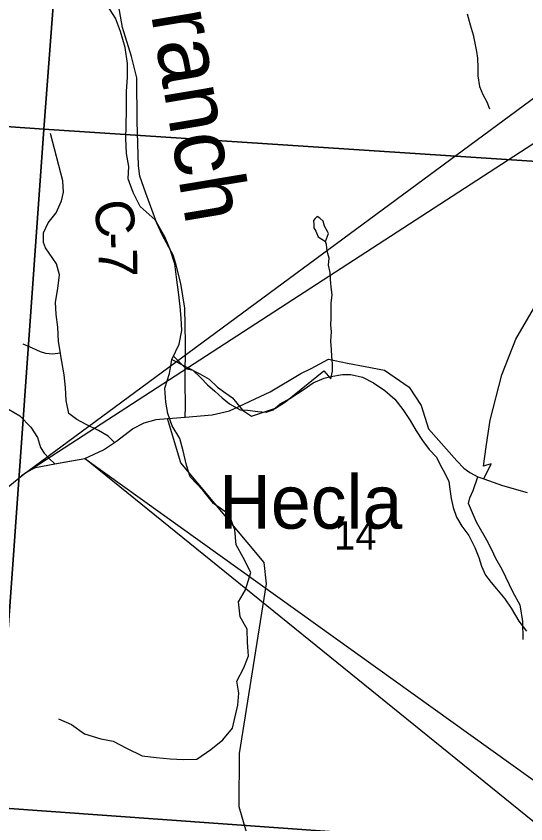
# Model space of a CAD drawing. Extents: x 0 to 34, y 0 to 22.
# Drawn here: x 4.64 to 5.391, y 16.363 to 17.554 of the extents above; entities that cross this region are included whole.
import ezdxf

# ---------------------------------------------------------------- set-up
doc = ezdxf.new("R2010")
doc.units = 0
for name, color, linetype in [('GM_X_Corporation', 7, 'Continuous'), ('GM_X_County_Road', 7, 'Continuous'), ('GM_X_County_Road_Text', 7, 'Continuous'), ('GM_X_Minor_Lake', 7, 'Continuous'), ('GM_X_Minor_River', 7, 'Continuous'), ('GM_X_Minor_River_Text', 7, 'Continuous'), ('GM_X_Section_Text', 7, 'Continuous'), ('GM_X_State_Route', 7, 'Continuous'), ('GM_X_Township_Road', 7, 'Continuous'), ('GM_X_Unincorporated_Location', 7, 'Continuous'), ('GM_X_Unincorporated_Text', 7, 'Continuous'), ('SH_Text', 7, 'Continuous')]:
    doc.layers.add(name, color=color, linetype=linetype)

msp = doc.modelspace()

# ---------------------------------------------------------------- linework, layer by layer
at = {"layer": 'GM_X_Corporation'}
for points in [[(4.7598, 18.4308), (4.6804, 17.3872), (3.6641, 17.4586), (3.742, 18.4953)], [(4.7598, 18.4308), (5.775, 18.3681), (5.6845, 17.321), (4.6804, 17.3872)], [(3.6641, 17.4586), (4.6804, 17.3872), (4.6087, 16.3871), (3.6056, 16.4577)], [(4.6804, 17.3872), (5.6845, 17.321), (5.612, 16.3148), (5.6072, 16.3154), (4.6087, 16.3871)], [(4.6087, 16.3871), (5.6072, 16.3154), (5.5415, 15.2956), (4.5353, 15.3628)]]:
    msp.add_lwpolyline(points, close=True, dxfattribs=at)
at = {"layer": 'GM_X_County_Road'}
for points in [[(4.8886, 16.9624), (4.8894, 16.9787), (4.8887, 17.0141), (4.8892, 17.0726), (4.8884, 17.1231), (4.8823, 17.1597), (4.875, 17.1887), (4.8711, 17.2013), (4.8646, 17.2132), (4.8547, 17.2313), (4.8468, 17.2482), (4.831, 17.2926), (4.8221, 17.3179), (4.8198, 17.3327), (4.8178, 17.3985), (4.8173, 17.4627), (4.8096, 17.494), (4.7965, 17.5369), (4.7918, 17.5617), (4.7849, 17.5918), (4.7834, 17.6281)], [(4.3389, 17.135), (4.339, 17.1096), (4.352, 17.0964), (4.3677, 17.087), (4.388, 17.0816), (4.4115, 17.0785), (4.4326, 17.0754), (4.4522, 17.0712), (4.4713, 17.062), (4.4975, 17.0467), (4.5233, 17.0271), (4.5427, 17.0142), (4.5599, 17.0055), (4.599, 16.9891), (4.62, 16.9791), (4.6451, 16.9642), (4.6614, 16.9475), (4.6713, 16.9325), (4.6755, 16.9179), (4.681, 16.9095), (4.6884, 16.9017), (4.6965, 16.8937)], [(4.7848, 16.9253), (4.7877, 16.9272), (4.8111, 16.9451), (4.8283, 16.9539), (4.8458, 16.9589), (4.8625, 16.9605)], [(4.8625, 16.9605), (4.87, 16.9612), (4.8886, 16.9624)], [(4.9838, 16.3357), (4.9681, 16.3879), (4.9688, 16.4668), (5.0088, 16.717), (5.0052, 16.7481), (4.8823, 16.8951), (4.8625, 16.9605)], [(4.6965, 16.8937), (4.7043, 16.8952), (4.7411, 16.9014), (4.7682, 16.9143), (4.7848, 16.9253)]]:
    msp.add_lwpolyline(points, dxfattribs=at)
at = {"layer": 'GM_X_Minor_Lake'}
for points in [[(5.0832, 17.2583), (5.0802, 17.2553), (5.0779, 17.2522), (5.0782, 17.2462), (5.0782, 17.2416), (5.0812, 17.2367), (5.0846, 17.2283), (5.0956, 17.2214)], [(5.0956, 17.2214), (5.0998, 17.2332), (5.0986, 17.2362), (5.0941, 17.2438), (5.0923, 17.2514), (5.0873, 17.256), (5.0832, 17.2583)]]:
    msp.add_lwpolyline(points, dxfattribs=at)
at = {"layer": 'GM_X_Minor_River'}
for points in [[(4.7023, 16.5179), (4.7212, 16.5095), (4.7405, 16.4958), (4.7643, 16.4885), (4.7825, 16.4851), (4.8025, 16.4748), (4.8252, 16.4634), (4.846, 16.4607), (4.8668, 16.4591), (4.8865, 16.458), (4.9058, 16.4583), (4.9267, 16.4728), (4.9445, 16.4868), (4.9585, 16.5039), (4.9662, 16.5381), (4.9677, 16.5556), (4.9647, 16.5731), (4.975, 16.5929), (4.9822, 16.6108), (4.9804, 16.6302), (4.9801, 16.6499), (4.9699, 16.6682), (4.9673, 16.6903), (4.9779, 16.7078), (4.9856, 16.7336), (4.9743, 16.7557), (4.9637, 16.7743), (4.9619, 16.7964), (4.9536, 16.8188), (4.9305, 16.8352), (4.915, 16.855), (4.8962, 16.8744), (4.8909, 16.8919), (4.886, 16.9129), (4.8808, 16.9311), (4.8695, 16.9498), (4.8631, 16.9677), (4.8605, 16.9848), (4.8586, 17.0053), (4.8655, 17.0266), (4.8693, 17.0476), (4.88, 17.07), (4.8838, 17.0902), (4.8827, 17.1084), (4.8816, 17.1255), (4.879, 17.1469), (4.8764, 17.1651), (4.8734, 17.1887), (4.8666, 17.2097), (4.8587, 17.2283), (4.8444, 17.2531), (4.8225, 17.2732), (4.8119, 17.2934), (4.8048, 17.314), (4.8056, 17.3319), (4.8022, 17.3513), (4.8011, 17.3737), (4.8016, 17.3909), (4.8024, 17.4167), (4.8021, 17.4426), (4.8036, 17.4636), (4.804, 17.4837), (4.8003, 17.5073), (4.7936, 17.5309), (4.786, 17.5504), (4.774, 17.5698)], [(5.3043, 17.5571), (5.3089, 17.5407), (5.313, 17.5259), (5.3161, 17.5111), (5.3183, 17.5013), (5.3195, 17.4914), (5.3202, 17.4774), (5.3202, 17.4656), (5.3225, 17.45), (5.3274, 17.4383), (5.3331, 17.4272), (5.3372, 17.417)], [(5.093, 17.0309), (5.1034, 17.0191), (5.1057, 17.0301), (5.1061, 17.0411), (5.105, 17.0518), (5.1043, 17.0624), (5.1035, 17.0745), (5.1043, 17.0882), (5.1036, 17.0985), (5.104, 17.1079), (5.1041, 17.1303), (5.1052, 17.1428), (5.1037, 17.1542), (5.103, 17.166), (5.1023, 17.1755), (5.1, 17.1865), (5.1008, 17.1968), (5.0982, 17.207), (5.0971, 17.2169), (5.0956, 17.2214)], [(4.8717, 17.0525), (4.8896, 17.0344), (4.9002, 17.0317), (4.9119, 17.0202), (4.9217, 17.01), (4.9323, 17.0008), (4.9432, 16.9909), (4.9542, 16.9821), (4.9697, 16.9734), (4.9807, 16.9726), (4.9958, 16.9706), (5.0083, 16.9698), (5.0185, 16.9732), (5.0287, 16.9819), (5.0428, 16.9902), (5.0541, 16.9973), (5.064, 17.0037), (5.0776, 17.0132), (5.0936, 17.0199), (5.1034, 17.0226), (5.1208, 17.0252), (5.1329, 17.0255), (5.15, 17.0213), (5.1662, 17.0132), (5.1832, 17.0018), (5.1979, 16.9888), (5.2093, 16.9736), (5.2202, 16.9576), (5.2292, 16.9424), (5.2387, 16.928), (5.2481, 16.9147), (5.259, 16.9036), (5.2647, 16.8922), (5.2715, 16.8797), (5.2771, 16.8675), (5.279, 16.8561), (5.2808, 16.8424), (5.2838, 16.8292), (5.2887, 16.8151), (5.2966, 16.8018), (5.3068, 16.7881), (5.3155, 16.7702), (5.3215, 16.7554), (5.3256, 16.7429), (5.3316, 16.7296), (5.3395, 16.7189), (5.3475, 16.7094), (5.3599, 16.6946), (5.3693, 16.6809), (5.3807, 16.6619), (5.392, 16.6471)], [(4.8693, 17.0476), (4.9104, 17.0263), (4.924, 17.0183), (4.9365, 17.0066), (4.9486, 16.9978), (4.9584, 16.991), (4.9731, 16.9728), (4.9864, 16.9641), (5.0219, 16.9755), (5.0366, 16.985), (5.093, 17.0309)]]:
    msp.add_lwpolyline(points, dxfattribs=at)
at = {"layer": 'GM_X_State_Route'}
for points in [[(4.8886, 16.9624), (4.9284, 16.9659), (4.9539, 16.9716), (5.0141, 16.9998), (5.0592, 17.0268), (5.0744, 17.034), (5.1001, 17.048), (5.1279, 17.0422), (5.1541, 17.037), (5.1824, 17.0317), (5.2191, 17.0066), (5.2364, 16.9798), (5.2473, 16.9451), (5.289, 16.8981), (5.2992, 16.8871), (5.3084, 16.8808), (5.3199, 16.8743), (5.3291, 16.8717), (5.3563, 16.8616), (5.3927, 16.8515)], [(4.7848, 16.9253), (4.7877, 16.9272), (4.8111, 16.9451), (4.8283, 16.9539), (4.8458, 16.9589), (4.8625, 16.9605)], [(4.8625, 16.9605), (4.87, 16.9612), (4.8886, 16.9624)], [(4.6965, 16.8937), (4.7043, 16.8952), (4.7411, 16.9014), (4.7682, 16.9143), (4.7848, 16.9253)], [(4.5384, 16.34), (4.5538, 16.3822), (4.563, 16.4086), (4.5659, 16.4241), (4.5628, 16.4446), (4.548, 16.4885), (4.5435, 16.5125), (4.5427, 16.5299), (4.5448, 16.5462), (4.5582, 16.5748), (4.575, 16.606), (4.5826, 16.6332), (4.5819, 16.6579), (4.5762, 16.702), (4.5743, 16.7282), (4.5787, 16.7637), (4.5908, 16.806), (4.6018, 16.8286), (4.6253, 16.8578), (4.6537, 16.8809), (4.6682, 16.8882), (4.6965, 16.8937)]]:
    msp.add_lwpolyline(points, dxfattribs=at)
at = {"layer": 'GM_X_Township_Road'}
for points in [[(4.7848, 16.9253), (4.7754, 16.9345), (4.761, 16.9426), (4.7429, 16.9515), (4.7289, 16.9588), (4.7172, 16.9679), (4.7132, 16.987), (4.7125, 17.006), (4.7104, 17.025), (4.7056, 17.0527), (4.705, 17.0569), (4.7023, 17.074), (4.7013, 17.0949), (4.6988, 17.1136), (4.6978, 17.1322), (4.701, 17.1523), (4.7037, 17.1724), (4.6989, 17.1884), (4.6828, 17.2121), (4.6802, 17.2197), (4.6802, 17.2341), (4.6868, 17.2489), (4.6986, 17.2637), (4.7067, 17.2815), (4.7095, 17.294), (4.7084, 17.3107), (4.6903, 17.3808)], [(5.3325, 16.9189), (5.333, 16.9221), (5.3381, 16.958), (5.3555, 17.0248), (5.3763, 17.0775), (5.4092, 17.1339)], [(4.705, 17.0569), (4.6931, 17.0551), (4.6836, 17.0563), (4.6757, 17.0586), (4.6636, 17.064), (4.65, 17.0702)], [(5.3316, 16.8912), (5.3284, 16.8901), (5.3325, 16.9189)], [(5.3291, 16.8717), (5.3396, 16.8939), (5.3316, 16.8912)], [(5.3436, 16.7603), (5.3351, 16.7775), (5.3181, 16.8079), (5.3065, 16.8352), (5.3084, 16.8436), (5.3134, 16.8546), (5.3199, 16.8743)], [(5.3827, 16.6827), (5.3822, 16.6856), (5.3722, 16.704), (5.356, 16.7381), (5.3465, 16.7543), (5.3436, 16.7603)], [(5.3867, 16.6348), (5.3864, 16.6615), (5.3827, 16.6827)]]:
    msp.add_lwpolyline(points, dxfattribs=at)
at = {"layer": 'GM_X_Unincorporated_Location'}
msp.add_line((4.8982, 16.9672), (4.8982, 16.9672), dxfattribs=at)
at = {"layer": 'SH_Text'}
for points in [[(4.6475, 16.8758), (5.8902, 17.7932), (5.8902, 17.6825)], [(4.7411, 16.9014), (5.9375, 16.0436), (5.9375, 15.9329)]]:
    msp.add_lwpolyline(points, close=True, dxfattribs=at)
msp.add_lwpolyline([(4.6475, 16.8758), (4.6537, 16.8809), (4.6682, 16.8882), (4.6965, 16.8937), (4.7411, 16.9014)], dxfattribs=at)

# ---------------------------------------------------------------- texts
at = {"layer": 'GM_X_County_Road_Text'}
for s, rotation, p in [('C', 279.9596, (4.7525, 17.278)), ('-', 271.8581, (4.7604, 17.2341)), ('7', 270.7702, (4.7611, 17.2111))]:
    msp.add_text(s, height=0.0568, rotation=rotation, dxfattribs=at).set_placement(p)
at = {"layer": 'GM_X_Minor_River_Text'}
msp.add_text('Branch', height=0.09475, rotation=279.4884, dxfattribs=at).set_placement((4.8243, 17.64))
at = {"layer": 'GM_X_Section_Text'}
msp.add_text('14', height=0.04186, rotation=0, dxfattribs=at).set_placement((5.1084, 16.7673))
at = {"layer": 'GM_X_Unincorporated_Text'}
msp.add_text('Hecla', height=0.07898, rotation=0, dxfattribs=at).set_placement((4.9388, 16.7981))

doc.saveas('drawing.dxf')
